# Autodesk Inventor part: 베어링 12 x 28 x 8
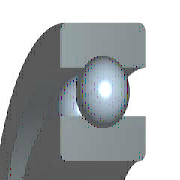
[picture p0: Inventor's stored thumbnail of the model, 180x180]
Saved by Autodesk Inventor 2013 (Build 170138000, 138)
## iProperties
IsCustomPart: 1
Created: 2012-02
Part Number: 베어링 12 x 28 x 8
Material: 강철, 연강
Description: 깊은 그루브 볼 베어링
Document SubType Name: Modeling
Standard: KS B 2023
Designer: mduedu
Standards Organization: KS
Language: ko-KR
Size Designation: 6001 - 12 x 28 x 8
Categories: <MemberInstance><Categories><Category DisplayName="샤프트 부품" InternalName="7f7aeb1f-a693-4053-b835-cee3144e0d98" Mnemonic="SHFT"><Category DisplayName="베어링" Inter
Density: 7.86 g/cm^3
Mass: 21.4855 g
Surface Area: 31.1809 cm^2
Volume: 2.73352 cm^3
Author: mduedu
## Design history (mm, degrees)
sketch "스케치" dims "d0" = 4.16 (= -0.26 x WD + 0.26 x BD)
  geometry: L1 (1.92, 10)-(6.08, 10); L2 (4, 10)-(4, 7.92); L3 (4, 10)-(4, 12.08); L4 (2.454, 8.608)-(0, 8.608); L5 (0, 6)-(8, 6); L6 (2.454, 11.392)-(0, 11.392); L7 (0, 14)-(8, 14); L8 (8, 6)-(8, 8.608); L9 (5.546, 8.608)-(8, 8.608); L10 (5.546, 11.392)-(8, 11.392); L11 (8, 14)-(8, 11.392); L12 (-1.4, 0)-(8.4, 0) reference; L13 (0, -0.3)-(0, 5.3) reference
  constraints: 22 end point, 4 point on line, 2 collinear, 2 perpendicular, 2 symmetric about line, 1 midpoint, 1 parallel, 14 other
  dimensions: "d9" = 12 diameter of L5 L12 (= WD); "d11" = 28 diameter of L7 L12 (= BD); "d12" = 8 distance between parallel lines of L8 L13 (= KB); "d13" = 17.216 diameter of L9 L12 (= 0.326 x BD + 0.674 x WD)
revolve "본체" stored, may be unused: angle "d6" = 90 deg
revolve "볼" stored, may be unused: angle "d7" = 90 deg
pattern_circular "IDS_ARRAYBALL[SIMPL:T]" dims angle "d3" = 360 deg
body "Solid1"
fillet "모깎기1" dims "d1" = 0.3 (= KRS)
other parameters: "WD" = 12 [user parameter; used in 5 equation terms], "BD" = 28 [user parameter; used in 5 equation terms], "KB" = 8 [user parameter; used in 1 equation term], "KRS" = 0.3 [user parameter; used in 1 equation term], "d4" = 0, "d5" = 0, "d8" = 0, "d14" = 0, "d15" = 0, "BBA" = 0 [user parameter], "BC0" = 2360000 [user parameter], "BC" = 5070000 [user parameter], "BR" = 14 (= 0.5 x BD) [user parameter], "WR" = 6 (= 0.5 x WD) [user parameter]
